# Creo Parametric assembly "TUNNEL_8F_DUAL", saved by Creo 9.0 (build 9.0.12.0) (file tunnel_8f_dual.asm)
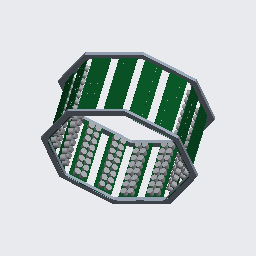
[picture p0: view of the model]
Units: millimeter Newton Second (mmNs); MM, TONNE, SECS

Created from: XX_MMNS_ASM_DESIGN_ABS.ASM

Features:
  1. datum plane "ASM_RIGHT"
  2. datum plane "ASM_TOP"
  3. datum plane "ASM_FRONT"
  4. coordinate system
  5. coordinate system
  6. component "FACEPAIR_8F"
  7. coordinate system
  8. component "FACEPAIR_8F"
  9. coordinate system
  10. component "FACEPAIR_8F"
  11. coordinate system
  12. component "FACEPAIR_8F"
  13. coordinate system
  14. component "FACEPAIR_8F"
  15. coordinate system
  16. component "FACEPAIR_8F"
  17. coordinate system
  18. component "FACEPAIR_8F"
  19. coordinate system
  20. component "FACEPAIR_8F"
  21. coordinate system
  22. component "RING_8F"
  23. coordinate system
  24. component "RING_8F"

Other named items: ACS0, ACS1, ACS2, ACS3, ACS4, ACS5, ACS6, ACS7, ACS8, ACS9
